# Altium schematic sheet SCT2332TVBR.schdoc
size 127 x 101 mm
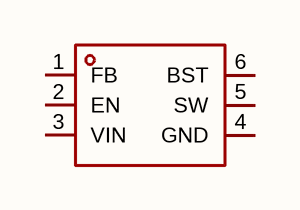
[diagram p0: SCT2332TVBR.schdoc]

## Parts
U?  sct2332tvbr  [TSOT-23-6_L2.9-W1.6-P0.95-LS2.8-BL]  (value not drawn)

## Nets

Not connected (* = marked no-connect by the designer): U? 1(FB) 2(EN) 3(VIN) 4(GND) 5(SW) 6(BST)

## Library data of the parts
U? = sct2332tvbr: 功能类型:降压型;工作电压:3.8V~32V;输出电压:-;输出电流:3A;输出类型:可调;; Manufacturer: SCT(芯洲科技); AddInBom: yes; ModelId: 2c4039b5b88644c1bda4b4ba9e971667; ModelName: TSOT-23-6_L2.9-W1.6-H1.1-LS2.8-P0.95; ModelTransform: 110.236,114.173,0,90,0,0,0,0,0; Function: 降压型; Output Current: 3A; Frequency - Switching: 360kHz~440kHz; Synchronous Rectifier: 是; Number of Outputs: 1; Topology: 降压式; Quiescent Current: 250uA; Switch tube (built-in/external): 内置; Output Type: 可调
